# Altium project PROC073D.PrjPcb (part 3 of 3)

## Sheet PROC073D_Can_Interface.SchDoc: CAN Interface
size 431 x 279 mm; Date: Not shown in title block; ApprovedBy: Not shown in title block; CheckedBy: Not shown in title block; Author: Not shown in title block; CompanyName: Not shown in title block; DrawnBy: Charles F. Oladimeji; Engineer: Not shown in title block; Organization: Not shown in title block; Address1: Not shown in title block; Address2: Not shown in title block; Address3: Not shown in title block; Address4: Not shown in title block; DocumentNumber: 12; Revision: Use project parameter SCH_Rev; SheetNumber: 12; SheetTotal: 13; PageSetup: Record=PageOptions¦CenterHorizontal=True¦CenterVertical=True¦PrintScale=1.00¦XCorrection=1.00¦YCorrection=1.00¦PrintKind=0¦BorderSize=5000000¦LeftOffset=0¦BottomOffset=0¦Orientation=2¦PaperLength=1000¦PaperWidth=1000¦Scale=100¦PaperSource=15¦PrintQuality=600¦MediaType=1¦DitherType=10¦PaperKind=Letter¦PrintScaleMode=1
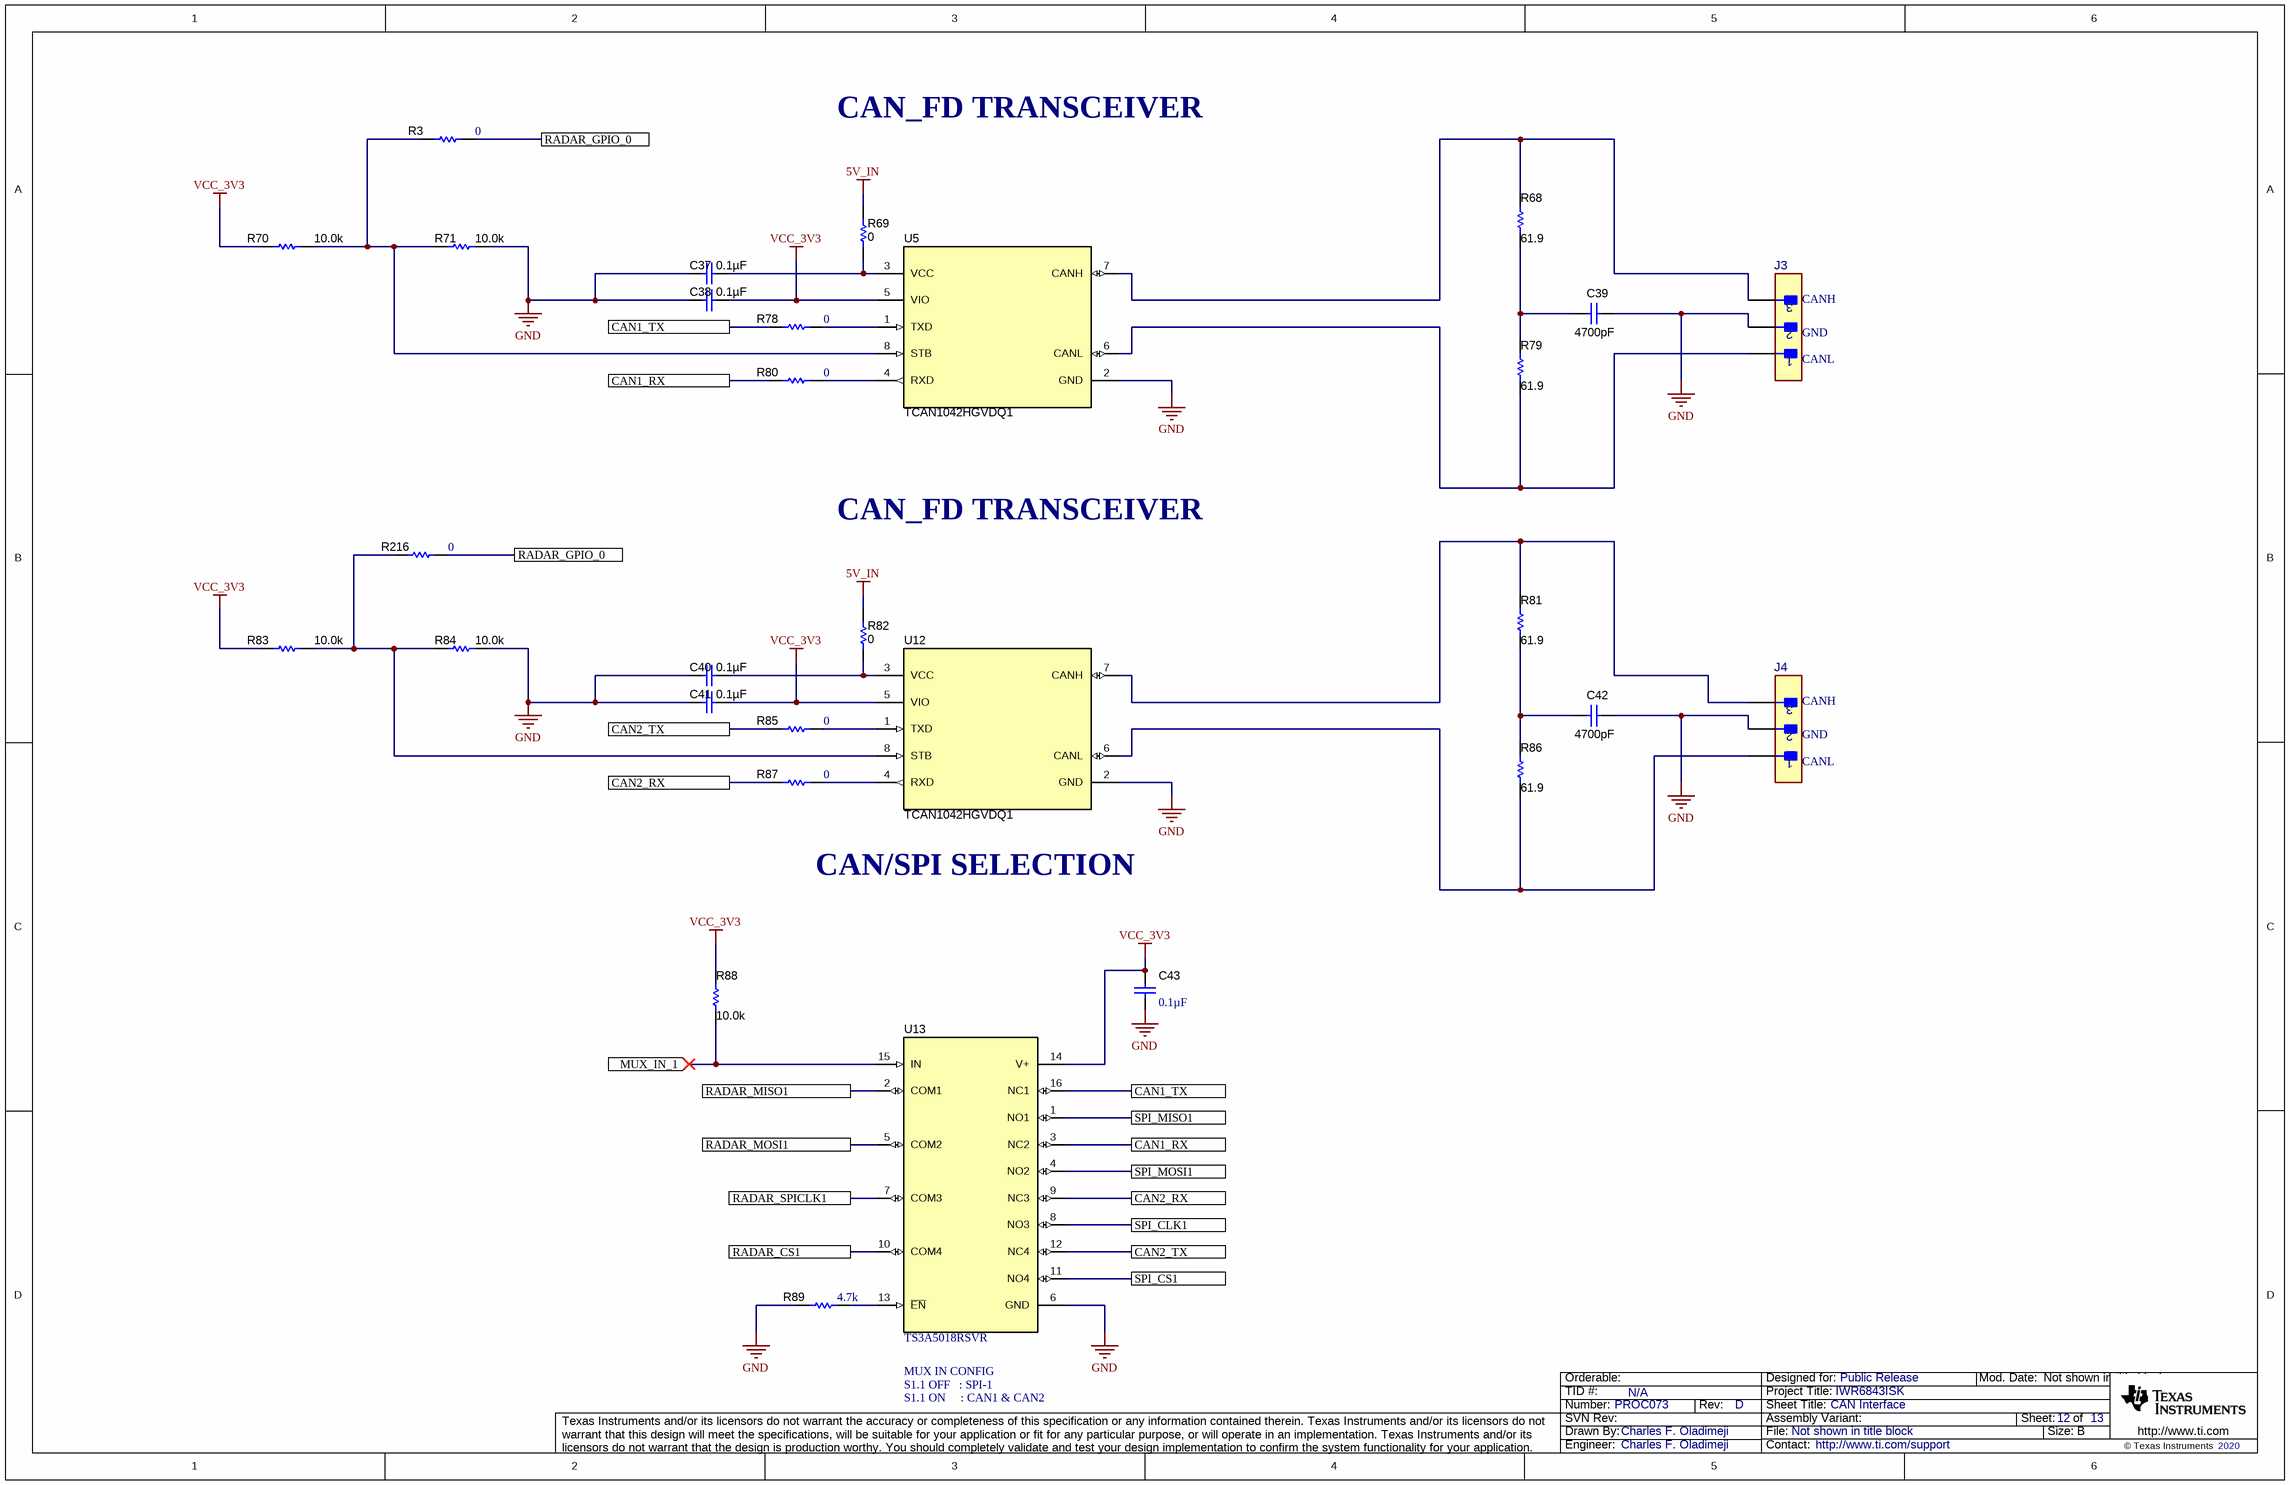
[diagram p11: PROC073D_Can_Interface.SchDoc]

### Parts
C37  ValueDisplayed: 0.1µF  [0402L]  (hidden comment: C0402C104K8RACTU)
C38  ValueDisplayed: 0.1µF  [0402L]  (hidden comment: C0402C104K8RACTU)
C39  ValueDisplayed: 4700pF  [0402L]  (hidden comment: GCM155R71H472KA37D)
C40  ValueDisplayed: 0.1µF  [0402L]  (hidden comment: C0402C104K8RACTU)
C41  ValueDisplayed: 0.1µF  [0402L]  (hidden comment: C0402C104K8RACTU)
C42  ValueDisplayed: 4700pF  [0402L]  (hidden comment: GCM155R71H472KA37D)
C43  ValueDisplayed: 0.1µF  [0402]  (hidden comment: C0402C104K8RACTU)
J3  M50-3930342  [FP-M50-3930342_HDR3-MFG]  (value not drawn)
J4  M50-3930342  [FP-M50-3930342_HDR3-MFG]  (value not drawn)
R3  ValueDisplayed: 0  [0402]  (hidden comment: ERJ-2GE0R00X)
R68  ValueDisplayed: 61.9  [0402L]  (hidden comment: CRCW040261R9FKED)
R69  ValueDisplayed: 0  [0201_Silk]  (hidden comment: CRCW02010000Z0ED)
R70  ValueDisplayed: 10.0k  [0402L]  (hidden comment: CRCW040210K0FKED)
R71  ValueDisplayed: 10.0k  [0402L]  (hidden comment: CRCW040210K0FKED)
R78  ValueDisplayed: 0  [0402]  (hidden comment: ERJ-2GE0R00X)
R79  ValueDisplayed: 61.9  [0402L]  (hidden comment: CRCW040261R9FKED)
R80  ValueDisplayed: 0  [0402]  (hidden comment: ERJ-2GE0R00X)
R81  ValueDisplayed: 61.9  [0402L]  (hidden comment: CRCW040261R9FKED)
R82  ValueDisplayed: 0  [0201_Silk]  (hidden comment: CRCW02010000Z0ED)
R83  ValueDisplayed: 10.0k  [0402L]  (hidden comment: CRCW040210K0FKED)
R84  ValueDisplayed: 10.0k  [0402L]  (hidden comment: CRCW040210K0FKED)
R85  ValueDisplayed: 0  [0402]  (hidden comment: ERJ-2GE0R00X)
R86  ValueDisplayed: 61.9  [0402L]  (hidden comment: CRCW040261R9FKED)
R87  ValueDisplayed: 0  [0402]  (hidden comment: ERJ-2GE0R00X)
R88  ValueDisplayed: 10.0k  [0402L]  (hidden comment: CRCW040210K0FKED)
R89  ValueDisplayed: 4.7k  [0402]  (hidden comment: CRCW04024K70JNED)
R216  ValueDisplayed: 0  [0402]  (hidden comment: ERJ-2GE0R00X)
U5  TCAN1042HGVDQ1  [D0008A_L]
U12  TCAN1042HGVDQ1  [D0008A_L]
U13  TS3A5018RSVR  [RSV0016A]

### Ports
CAN1_RX, CAN1_TX, CAN2_RX, CAN2_TX, MUX_IN_1 (in), RADAR_CS1, RADAR_GPIO_0, RADAR_MISO1, RADAR_MOSI1, RADAR_SPICLK1, SPI_CLK1, SPI_CS1, SPI_MISO1, SPI_MOSI1

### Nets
5V_IN: R69.2 R82.2
GND: C37.1 C38.1 C39.1 C40.1 C41.1 C42.1 C43.2 J3.2 J4.2 R71.2 R84.2 R89.1 U5.2(GND) U12.2(GND) U13.6(GND)
VCC_3V3: C38.2 C41.2 C43.1 R70.1 R83.1 R88.2 U5.5(VIO) U12.5(VIO) U13.14(V+)
CAN1_RX: R80.1 U13.3(NC2) ; port CAN1_RX
CAN1_TX: R78.1 U13.16(NC1) ; port CAN1_TX
CAN2_RX: R87.1 U13.9(NC3) ; port CAN2_RX
CAN2_TX: R85.1 U13.12(NC4) ; port CAN2_TX
MUX_IN_1: R88.1 U13.15(IN) ; port MUX_IN_1
RADAR_CS1: U13.10(COM4) ; port RADAR_CS1
RADAR_GPIO_0: R3.2 R216.2 ; port RADAR_GPIO_0
RADAR_MISO1: U13.2(COM1) ; port RADAR_MISO1
RADAR_MOSI1: U13.5(COM2) ; port RADAR_MOSI1
RADAR_SPICLK1: U13.7(COM3) ; port RADAR_SPICLK1
SPI_CLK1: U13.8(NO3) ; port SPI_CLK1
SPI_CS1: U13.11(NO4) ; port SPI_CS1
SPI_MISO1: U13.1(NO1) ; port SPI_MISO1
SPI_MOSI1: U13.4(NO2) ; port SPI_MOSI1
NetC37_2: C37.2 R69.1 U5.3(VCC)
NetC39_2: C39.2 R68.1 R79.2
NetC40_2: C40.2 R82.1 U12.3(VCC)
NetC42_2: C42.2 R81.1 R86.2
NetJ3_1: J3.1 R79.1 U5.6(CANL)
NetJ3_3: J3.3 R68.2 U5.7(CANH)
NetJ4_1: J4.1 R86.1 U12.6(CANL)
NetJ4_3: J4.3 R81.2 U12.7(CANH)
NetR3_1: R3.1 R70.2 R71.1 U5.8(STB)
NetR78_2: R78.2 U5.1(TXD)
NetR80_2: R80.2 U5.4(RXD)
NetR83_2: R83.2 R84.1 R216.1 U12.8(STB)
NetR85_2: R85.2 U12.1(TXD)
NetR87_2: R87.2 U12.4(RXD)
NetR89_2: R89.2 U13.13(~{EN})

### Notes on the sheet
- CAN_FD TRANSCEIVER
- (near J3) CANH
- (near J3) GND
- (near J3) CANL
- (near J4) CANH
- (near J4) GND
- (near J4) CANL
- CAN/SPI SELECTION
- MUX IN CONFIG
- S1.1 OFF   : SPI-1
- S1.1 ON     : CAN1 & CAN2

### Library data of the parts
C37 C38 C40 C41 = CMP-0078241-1: CAP, CERM, 0.1 µF, 10 V,+/- 10%, X7R, 0402; Manufacturer: Kemet; TaMin_C: -55°C; Polarized: N; SizeAreaWB_mm2: 3; U/M: EA; Value: 0.1uF; TaMax_C: 125°C; SizeZ_mm: 0.6; SizeX_mm: 1; SizeY_mm: 0.5; Cap_Case: 0402; Value2: 10V; CompType: Capacitor; Cap_F: 100nF; AEC Category: Q200
C39 C42 = CMP-0006361-2: CAP, CERM, 4700 pF, 50 V, +/- 10%, X7R, AEC-Q200 Grade 1, 0402; Manufacturer: MuRata; TaMin_C: -55°C; Polarized: N; SizeAreaWB_mm2: 3; Value1: Unknown; U/M: EA; Value: 4700pF; TaMax_C: 125°C; SizeZ_mm: 0.6; SizeX_mm: 1; SizeY_mm: 0.5; Cap_Case: 0402; Value2: 50V; AEC Qualified: Y; Cap_F: 4.7nF; AEC Category: Q200
C43 = CMP-0078241-1: CAP, CERM, 0.1 µF, 10 V,+/- 10%, X7R, 0402; Manufacturer: Kemet; TaMin_C: -55°C; Polarized: N; SizeAreaWB_mm2: 3; U/M: EA; Value: 0.1uF; TaMax_C: 125°C; SizeZ_mm: 0.6; SizeX_mm: 1; SizeY_mm: 0.5; Value2: 10V; CompType: Capacitor; Cap_F: 100nF; AEC Category: Q200
J3 J4 = CMP-0087785-1: CONN HEADER R/A 3POS 1.27MM; Manufacturer: Harwin; Row_Count: 1; Current_A: 1A; ContactFinish: Gold,Nickel
R3 R78 R80 R85 R87 R216 = CMP-0026992-3: RES, 0, 5%, 0.1 W, AEC-Q200 Grade 0, 0402; Manufacturer: Panasonic; Power_W: 100mW; TempCo: 600 ppm/C; Value_Code: 0000; Value: 0; EIA_Code: E24; SizeX_mm: 1; SizeY_mm: 0.5; SizeZ_mm: 0.6; Value2: 0.1W; CompType: Resistor; AEC Qualified: Y; VDC_V: 50V; AEC Category: Q200; SizeAreaWB_mm2: 3; INSTALLATION: DNP
R68 R79 R81 R86 = CMP-0026491-2: RES, 61.9, 1%, 0.063 W, AEC-Q200 Grade 0, 0402; Manufacturer: Vishay-Dale; Power_W: 63mW; TempCo: 100 ppm/C; Value_Code: 61R9; Value: 61.9; EIA_Code: E96; SizeX_mm: 1; SizeY_mm: 0.5; SizeZ_mm: 0.6; Value2: 0.063W; AEC Qualified: Y; VDC_V: 50V; AEC Category: Q200; AEC Grade: 0
R69 R82 = CMP-0027008-4: RES, 0, 5%, 0.05 W, 0201; Manufacturer: Vishay-Dale; Power_W: 50mW; TempCo: ppm/C; Value_Code: 0000; Value: 0; EIA_Code: E24; SizeX_mm: 0.6; SizeY_mm: 0.3; SizeZ_mm: 0.26; Value2: 0.05W; SizeArea_mm2: 0.18; AEC Qualified: N; AEC Category: Q200
R70 R71 R83 R84 R88 = CMP-0025958-3: RES, 10.0 k, 1%, 0.063 W, AEC-Q200 Grade 0, 0402; Manufacturer: Vishay-Dale; Power_W: 63mW; TempCo: 100 ppm/C; Value_Code: 10k0; Value: 10.0k; EIA_Code: E96; Res_ohm: 10k; SizeX_mm: 1; SizeY_mm: 0.5; SizeZ_mm: 0.6; Value2: 0.063W; AEC Qualified: Y; VDC_V: 50V; AEC Category: Q200; AEC Grade: 0
R89 = CMP-0026938-5: RES, 4.7 k, 5%, 0.063 W, AEC-Q200 Grade 0, 0402; Manufacturer: Vishay-Dale; Power_W: 63mW; TempCo: 200 ppm/C; Value_Code: 4k70; Value: 4.7k; EIA_Code: E24; SizeX_mm: 1; SizeY_mm: 0.5; SizeZ_mm: 0.6; Value2: 0.063W; AEC Qualified: Y; VDC_V: 50V; AEC Category: Q200; AEC Grade: 0
U5 U12 = CMP-0075992-1: Automotive Fault Protected CAN Transceiver With Flexible Data-Rate, D0008A (SOIC-8); Manufacturer: Texas Instruments; Alternate PartNumber: TCAN1042HGVDRQ1; SizeAreaWB_mm2: 56.58; SizeArea_mm2: 30.38; SizeZ_mm: 1.75; SizeY_mm: 6.2; U/M: EA; CompType: IC; SizeX_mm: 4.9
U13 = CMP-0067415-1: 10-Ohm Quad SPDT Analog Switch, RSV0016A (UQFN-16); Alternate Manufacturer: Texas Instruments; SizeAreaWB_mm2: 10.08; U/M: EA; SizeZ_mm: 0.55; SizeX_mm: 1.8; SizeY_mm: 2.6; SizeArea_mm2: 4.68; CompType: IC

## Sheet PROC073D_EVM_Hardware.SchDoc: Hardware
size 431 x 279 mm; Date: Not shown in title block; ApprovedBy: Not shown in title block; CheckedBy: Not shown in title block; Author: Not shown in title block; CompanyName: Not shown in title block; DrawnBy: Charles F. Oladimeji; Engineer: Not shown in title block; Organization: Not shown in title block; Address1: Not shown in title block; Address2: Not shown in title block; Address3: Not shown in title block; Address4: Not shown in title block; DocumentNumber: 13; Revision: Use project parameter SCH_Rev; SheetNumber: 13; SheetTotal: 13; PageSetup: Record=PageOptions¦CenterHorizontal=True¦CenterVertical=True¦PrintScale=1.00¦XCorrection=1.00¦YCorrection=1.00¦PrintKind=0¦BorderSize=5000000¦LeftOffset=0¦BottomOffset=0¦Orientation=2¦PaperLength=1000¦PaperWidth=1000¦Scale=100¦PaperSource=15¦PrintQuality=600¦MediaType=1¦DitherType=10¦PaperKind=Letter¦PrintScaleMode=1
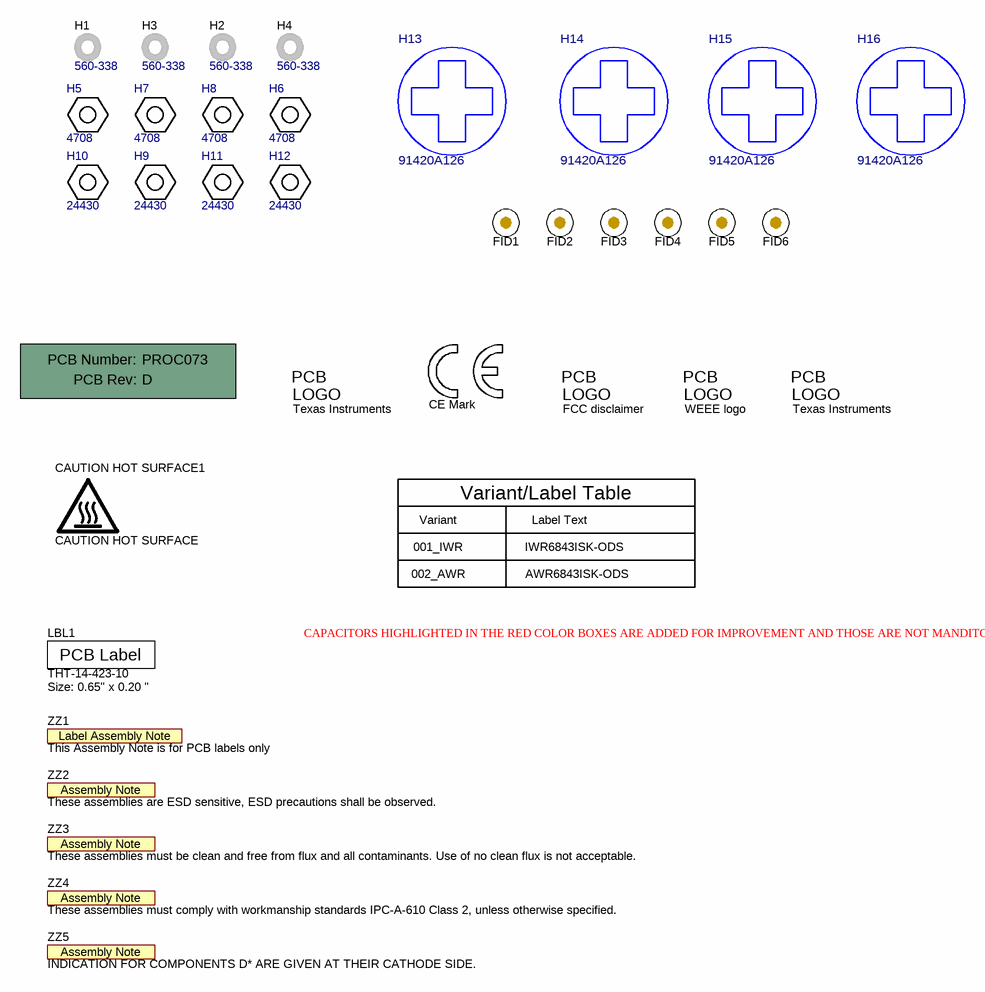
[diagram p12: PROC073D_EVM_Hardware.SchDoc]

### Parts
!PCB  Printed Circuit Board  (value not drawn)  (mechanical)
CAUTION_HOT_SURFACE1  CAUTION HOT SURFACE  [IEC_HotSurface_Small]  (no BOM)
FID1  Fiducial  [Fiducial10-20]  (value not drawn)
FID2  Fiducial  [Fiducial10-20]  (value not drawn)
FID3  Fiducial  [Fiducial10-20]  (value not drawn)
FID4  Fiducial  [Fiducial10-20]  (value not drawn)
FID5  Fiducial  [Fiducial10-20]  (value not drawn)
FID6  Fiducial  [Fiducial10-20]  (value not drawn)
H1  560-338  (mechanical)
H2  560-338  (mechanical)
H3  560-338  (mechanical)
H4  560-338  (mechanical)
H5  4708  (mechanical)
H6  4708  (mechanical)
H7  4708  (mechanical)
H8  4708  (mechanical)
H9  24430  (mechanical)
H10  24430  (mechanical)
H11  24430  (mechanical)
H12  24430  (mechanical)
H13  91420A126  [FP-91420A126_SCREW_M3X0.5-MFG]  (mechanical)
H14  91420A126  [FP-91420A126_SCREW_M3X0.5-MFG]  (mechanical)
H15  91420A126  [FP-91420A126_SCREW_M3X0.5-MFG]  (mechanical)
H16  91420A126  [FP-91420A126_SCREW_M3X0.5-MFG]  (mechanical)
LBL1  THT-14-423-10  Note: Size: 0.65" x 0.20 "  [Label_650x200]
Logo1  Texas Instruments  [TI_Stacked_Overlay_Small]  (no BOM)
Logo2  CE Mark  [CE_Mark_5mm]  (no BOM)
Logo3  FCC disclaimer  [FCC_disclaimer]  (no BOM)
Logo4  WEEE logo  [WEEE_Minimum]  (no BOM)
Logo5  Texas Instruments  [TI_Symbol_Overlay_Small]  (no BOM)
ZZ1  This Assembly Note is for PCB labels only  [AssemblyNoteLabel]  (no BOM)
ZZ2  These assemblies are ESD sensitive, ESD precautions shall be observed.  [AssemblyNote]  (no BOM)
ZZ3  These assemblies must be clean and free from flux and all contaminants. Use of no clean flux is not acceptable.  [AssemblyNote]  (no BOM)
ZZ4  These assemblies must comply with workmanship standards IPC-A-610 Class 2, unless otherwise specified.  [AssemblyNote]  (no BOM)
ZZ5  INDICATION FOR COMPONENTS D* ARE GIVEN AT THEIR CATHODE SIDE.  [AssemblyNote]  (no BOM)

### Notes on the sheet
- Variant
- 001_IWR
- Variant/Label Table
- Label Text
- IWR6843ISK-ODS
- 002_AWR
- AWR6843ISK-ODS
- CAPACITORS HIGHLIGHTED IN THE RED COLOR BOXES ARE ADDED FOR IMPROVEMENT AND THOSE ARE NOT MANDITORY.

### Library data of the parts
!PCB = CMP-0003618-2: Manufacturer: Any; PartNumber: PROC073
CAUTION_HOT_SURFACE1 = CMP-0074837-1: IEC 61010-1 Hot Surface Warning; Library Reference: IEC_HotSurface; SymbolCreator: a0412235
FID1-FID6 = CMP-0077181-1: Fiducial mark.  There is nothing to buy or mount.
H1-H4 = CMP-0084015-1: Steel Plain Washer; Manufacturer: RS Pro
H5-H8 = CMP-0003742-1: HEX NUT 0.217" STEEL M3; Manufacturer: Keystone; CompType: Standoff
H9-H12 = CMP-0003759-1: HEX Standoff M3 Aluminum 5 MM; Manufacturer: Keystone
H13-H16 = CMP-0086605-1: Steel Phillips Flat Head Screws M3 x 0.5 mm Thread, 16 mm Long; Manufacturer: McMaster-Carr
LBL1 = CMP-0003625-1: Thermal Transfer Printable Labels, 0.650" W x 0.200" H - 10,000 per roll; Manufacturer: Brady; CompType: Label
Logo1 = CMP-0074838-1: Texas Instrument Corporate Signature; SymbolCreator: a0412235; Lib Reference: TI_Logo; Library Reference: Logo
Logo2 = CMP-0074844-1: SymbolCreator: a0412235
Logo3 = CMP-0074847-1: FCC_disclaimer; Library Reference: Logo
Logo4 = CMP-0074769-1
Logo5 = CMP-0074838-1: Texas Instrument Corporate Signature; Library Reference: Logo; SymbolCreator: a0412235; Lib Reference: TI_Logo
ZZ1 = CMP-0003616-3
ZZ2 = CMP-0077236-1
ZZ3 = CMP-0077237-1
ZZ4 ZZ5 = CMP-0077238-1

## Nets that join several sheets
5V_IN: PROC073D_PMIC (12 pins), PROC073D_Flash_USB_To_UART (D2.1 R90.1), PROC073D_HD_DCA_Conn (R141.1), PROC073D_Can_Interface (R69.2 R82.2)
CB_PMIC_1V0: PROC073D_PMIC (R199.2), PROC073D_Decoupling_caps (C2.2 C3.2 L2.1 L3.1), PROC073D_HD_Connector_60Pin (J1.1 J1.3), PROC073D_Temp_Current_sensor (U7.9)
CB_PMIC_1V2: PROC073D_PMIC (R193.2), PROC073D_Decoupling_caps (C64.2 L7.1), PROC073D_HD_Connector_60Pin (J1.5 J1.7), PROC073D_Temp_Current_sensor (U8.9)
CB_PMIC_1V8: PROC073D_PMIC (R192.2 R195.1), PROC073D_Decoupling_caps (C1.2 L1.1), PROC073D_HD_Connector_60Pin (J1.9), PROC073D_Temp_Current_sensor (U6.9)
CONN_5V: PROC073D_HD_Connector_60Pin (J1.2 J2.58 J2.59 J2.60), PROC073D_Flash_USB_To_UART (C50.1 R102.1 U16.8), PROC073D_HD_DCA_Conn (8 pins)
GND: PROC073D_PMIC (34 pins), PROC073D_IWR6843_Chip (77 pins), PROC073D_Decoupling_caps (46 pins), PROC073D_QSPI_Flash_section (C34.1 C35.1 U2.4 U2.9), PROC073D_HD_Connector_60Pin (23 pins), PROC073D_Temp_Current_sensor (23 pins), PROC073D_Flash_USB_To_UART (28 pins), PROC073D_HD_DCA_Conn (26 pins), PROC073D_SOP_Ctrl (5 pins), PROC073D_Can_Interface (15 pins)
PMIC_1V0: PROC073D_PMIC (5 pins), PROC073D_Temp_Current_sensor (U7.8 U7.10)
PMIC_1V2: PROC073D_PMIC (5 pins), PROC073D_Temp_Current_sensor (U8.8 U8.10)
PMIC_1V8: PROC073D_PMIC (5 pins), PROC073D_Temp_Current_sensor (U6.8 U6.10)
PMICOUT_3V3: PROC073D_PMIC (L11.1 R198.2 TP10.1), PROC073D_Flash_USB_To_UART (9 pins), PROC073D_SOP_Ctrl (S1.10 S1.11 S1.12)
RADAR_1P0_RF1: PROC073D_IWR6843_Chip (U1.G5 U1.H5 U1.J5), PROC073D_Decoupling_caps (7 pins)
RADAR_1P0_RF2: PROC073D_IWR6843_Chip (U1.C2 U1.D2), PROC073D_Decoupling_caps (8 pins)
RADAR_1V2: PROC073D_IWR6843_Chip (6 pins), PROC073D_Decoupling_caps (9 pins)
RADAR_1V4_APLL: PROC073D_IWR6843_Chip (U1.A10), PROC073D_Decoupling_caps (C22.2)
RADAR_1V4_SYNTH: PROC073D_IWR6843_Chip (U1.B13), PROC073D_Decoupling_caps (C18.2)
RADAR_1V8: PROC073D_IWR6843_Chip (6 pins), PROC073D_Decoupling_caps (11 pins)
RADAR_3V3: PROC073D_PMIC (R184.2 R200.2), PROC073D_IWR6843_Chip (7 pins), PROC073D_Decoupling_caps (5 pins), PROC073D_Temp_Current_sensor (U10.9)
RADAR_VBGAP: PROC073D_IWR6843_Chip (U1.B10), PROC073D_Decoupling_caps (C6.1)
RADAR_VOUT_PA: PROC073D_IWR6843_Chip (U1.A2 U1.B2), PROC073D_Decoupling_caps (5 pins)
VCC_3V3: PROC073D_PMIC (7 pins), PROC073D_QSPI_Flash_section (R43.2 R44.2 R49.2 R50.1), PROC073D_HD_Connector_60Pin (6 pins), PROC073D_Temp_Current_sensor (27 pins), PROC073D_HD_DCA_Conn (6 pins), PROC073D_Can_Interface (9 pins)
VCC_LD_SW_3V3: PROC073D_PMIC (6 pins), PROC073D_Temp_Current_sensor (U10.8 U10.10)
VPP_1P7: PROC073D_IWR6843_Chip (C31.2 U1.L13), PROC073D_HD_Connector_60Pin (J2.57 TP14.1)
CONN_RS232RX: PROC073D_HD_Connector_60Pin (R38.1), PROC073D_Flash_USB_To_UART (U15.7), PROC073D_HD_DCA_Conn (J6.55)
CONN_RS232TX: PROC073D_HD_Connector_60Pin (R40.1), PROC073D_Flash_USB_To_UART (U15.9), PROC073D_HD_DCA_Conn (J6.57)
MUX_IN_1: PROC073D_SOP_Ctrl (S1.4), PROC073D_Can_Interface (R88.1 U13.15)
MUX_IN_2: PROC073D_Flash_USB_To_UART (R100.1 U15.1 U15.5), PROC073D_SOP_Ctrl (S1.5)
PGOOD: PROC073D_PMIC (R179.1 R182.2 R198.1 R201.2), PROC073D_HD_Connector_60Pin (R13.2), PROC073D_HD_DCA_Conn (J6.13)
PMIC_CLK: PROC073D_PMIC (U4.3), PROC073D_SOP_Ctrl (R202.2)
PMIC_EN1: PROC073D_PMIC (R188.1 U4.7), PROC073D_HD_Connector_60Pin (R140.1)
RADAR_BSS_LOGGER: PROC073D_IWR6843_Chip (U1.H14), PROC073D_HD_Connector_60Pin (R60.2)
RADAR_CS1: PROC073D_IWR6843_Chip (R156.1 U1.E15), PROC073D_Can_Interface (U13.10)
RADAR_DMM_CLK: PROC073D_IWR6843_Chip (U1.N15), PROC073D_HD_Connector_60Pin (R15.1), PROC073D_HD_DCA_Conn (J6.15)
RADAR_DMM_SYNC: PROC073D_IWR6843_Chip (U1.N14), PROC073D_HD_Connector_60Pin (R17.1), PROC073D_HD_DCA_Conn (J6.17)
RADAR_DP0: PROC073D_IWR6843_Chip (U1.R4), PROC073D_HD_Connector_60Pin (R18.1), PROC073D_HD_DCA_Conn (J6.19)
RADAR_DP1: PROC073D_IWR6843_Chip (U1.P5), PROC073D_HD_Connector_60Pin (R19.1), PROC073D_HD_DCA_Conn (J6.21)
RADAR_DP2: PROC073D_IWR6843_Chip (U1.R5), PROC073D_HD_Connector_60Pin (R20.1), PROC073D_HD_DCA_Conn (J6.23)
RADAR_DP3: PROC073D_IWR6843_Chip (U1.P6), PROC073D_HD_Connector_60Pin (R21.1), PROC073D_HD_DCA_Conn (J6.25)
RADAR_DP4: PROC073D_IWR6843_Chip (U1.R7), PROC073D_HD_Connector_60Pin (R23.1), PROC073D_HD_DCA_Conn (J6.27)
RADAR_DP5: PROC073D_IWR6843_Chip (U1.P7), PROC073D_HD_Connector_60Pin (R26.1), PROC073D_HD_DCA_Conn (J6.29)
RADAR_DP6: PROC073D_IWR6843_Chip (U1.R8), PROC073D_HD_Connector_60Pin (R27.1), PROC073D_HD_DCA_Conn (J6.31)
RADAR_DP7: PROC073D_IWR6843_Chip (U1.P8), PROC073D_HD_Connector_60Pin (R28.1), PROC073D_HD_DCA_Conn (J6.33)
RADAR_DP8: PROC073D_HD_Connector_60Pin (R124.1), PROC073D_HD_DCA_Conn (R148.1)
RADAR_DP9: PROC073D_HD_Connector_60Pin (R125.1), PROC073D_HD_DCA_Conn (R149.1)
RADAR_DP10: PROC073D_HD_Connector_60Pin (R126.1), PROC073D_HD_DCA_Conn (R163.1)
RADAR_DP11: PROC073D_HD_Connector_60Pin (R127.1), PROC073D_HD_DCA_Conn (R164.1)
RADAR_DP12: PROC073D_HD_Connector_60Pin (R128.1), PROC073D_HD_DCA_Conn (R166.1)
RADAR_DP13: PROC073D_HD_Connector_60Pin (R129.1), PROC073D_HD_DCA_Conn (R167.1)
RADAR_DP14: PROC073D_HD_Connector_60Pin (R130.1), PROC073D_HD_DCA_Conn (R168.1)
RADAR_DP15: PROC073D_HD_Connector_60Pin (R132.1), PROC073D_HD_DCA_Conn (R170.1)
RADAR_GPIO_0: PROC073D_IWR6843_Chip (U1.H13), PROC073D_HD_Connector_60Pin (R65.1), PROC073D_Can_Interface (R3.2 R216.2)
RADAR_GPIO_1: PROC073D_IWR6843_Chip (U1.J13), PROC073D_HD_Connector_60Pin (R66.2), PROC073D_HD_DCA_Conn (R214.2)
RADAR_GPIO_2: PROC073D_PMIC (R185.2), PROC073D_IWR6843_Chip (U1.K13), PROC073D_HD_Connector_60Pin (R67.2), PROC073D_HD_DCA_Conn (D7.1)
RADAR_HOSTINTR1: PROC073D_IWR6843_Chip (R152.2 U1.P13), PROC073D_HD_Connector_60Pin (R10.2), PROC073D_HD_DCA_Conn (J6.10)
RADAR_LVDS_0M: PROC073D_IWR6843_Chip (U1.J15), PROC073D_HD_Connector_60Pin (R41.2), PROC073D_HD_DCA_Conn (R230.2)
RADAR_LVDS_0P: PROC073D_IWR6843_Chip (U1.J14), PROC073D_HD_Connector_60Pin (R39.2), PROC073D_HD_DCA_Conn (R229.2)
RADAR_LVDS_1M: PROC073D_IWR6843_Chip (U1.K15), PROC073D_HD_Connector_60Pin (R35.2), PROC073D_HD_DCA_Conn (R228.2)
RADAR_LVDS_1P: PROC073D_IWR6843_Chip (U1.K14), PROC073D_HD_Connector_60Pin (R33.2), PROC073D_HD_DCA_Conn (R227.2)
RADAR_LVDS_2M: PROC073D_HD_Connector_60Pin (R137.2), PROC073D_HD_DCA_Conn (R224.2)
RADAR_LVDS_2P: PROC073D_HD_Connector_60Pin (R136.2), PROC073D_HD_DCA_Conn (R223.2)
RADAR_LVDS_3M: PROC073D_HD_Connector_60Pin (R135.2), PROC073D_HD_DCA_Conn (R222.2)
RADAR_LVDS_3P: PROC073D_HD_Connector_60Pin (R134.2), PROC073D_HD_DCA_Conn (R221.2)
RADAR_LVDS_CLKM: PROC073D_IWR6843_Chip (U1.L15), PROC073D_HD_Connector_60Pin (R32.2), PROC073D_HD_DCA_Conn (R226.2)
RADAR_LVDS_CLKP: PROC073D_IWR6843_Chip (U1.L14), PROC073D_HD_Connector_60Pin (R30.2), PROC073D_HD_DCA_Conn (R225.2)
RADAR_LVDS_FRCLKM: PROC073D_IWR6843_Chip (U1.M15), PROC073D_HD_Connector_60Pin (R24.2), PROC073D_HD_DCA_Conn (R220.2)
RADAR_LVDS_FRCLKP: PROC073D_IWR6843_Chip (U1.M14), PROC073D_HD_Connector_60Pin (R22.2), PROC073D_HD_DCA_Conn (R219.2)
RADAR_LVDS_VALIDM: PROC073D_HD_Connector_60Pin (R133.2), PROC073D_HD_DCA_Conn (R218.2)
RADAR_LVDS_VALIDP: PROC073D_HD_Connector_60Pin (R131.2), PROC073D_HD_DCA_Conn (R217.2)
RADAR_MCUCLKOUT: PROC073D_IWR6843_Chip (U1.N8), PROC073D_HD_Connector_60Pin (R62.2)
RADAR_MISO1: PROC073D_IWR6843_Chip (U1.E14), PROC073D_Can_Interface (U13.2)
RADAR_MOSI1: PROC073D_IWR6843_Chip (U1.D13), PROC073D_Can_Interface (U13.5)
RADAR_MSS_LOGGER: PROC073D_IWR6843_Chip (U1.F14), PROC073D_HD_Connector_60Pin (R31.2), PROC073D_Flash_USB_To_UART (R96.2)
RADAR_NERR_OUT: PROC073D_IWR6843_Chip (R169.1 U1.N6), PROC073D_HD_Connector_60Pin (R59.2)
RADAR_NERRIN: PROC073D_IWR6843_Chip (R150.1 U1.N7), PROC073D_HD_Connector_60Pin (R58.2)
RADAR_NRST: PROC073D_IWR6843_Chip (U1.R3), PROC073D_HD_DCA_Conn (R171.1 U17.4)
RADAR_NRST_1: PROC073D_HD_Connector_60Pin (R42.1), PROC073D_HD_DCA_Conn (J6.59 R123.2 U17.1)
RADAR_OSC_CLKOUT: PROC073D_IWR6843_Chip (U1.A14), PROC073D_HD_Connector_60Pin (R61.2)
RADAR_PMIC_CLKOUT_SOP2: PROC073D_IWR6843_Chip (U1.P9), PROC073D_HD_Connector_60Pin (R63.2), PROC073D_SOP_Ctrl (R202.1 R203.1)
RADAR_QSPI_CS: PROC073D_IWR6843_Chip (U1.P11), PROC073D_QSPI_Flash_section (R50.2 U2.1)
RADAR_QSPI_D0: PROC073D_IWR6843_Chip (U1.R13), PROC073D_QSPI_Flash_section (R45.2)
RADAR_QSPI_D1: PROC073D_IWR6843_Chip (U1.N12), PROC073D_QSPI_Flash_section (R46.1)
RADAR_QSPI_D2: PROC073D_IWR6843_Chip (U1.R14), PROC073D_QSPI_Flash_section (R44.1 R47.1)
RADAR_QSPI_D3: PROC073D_IWR6843_Chip (U1.P12), PROC073D_QSPI_Flash_section (R49.1 R51.2)
RADAR_QSPI_SCLK: PROC073D_IWR6843_Chip (U1.R12), PROC073D_QSPI_Flash_section (R48.2)
RADAR_RS232RX: PROC073D_IWR6843_Chip (R154.1 U1.N4), PROC073D_Flash_USB_To_UART (U15.6)
RADAR_RS232TX: PROC073D_IWR6843_Chip (R153.1 U1.N5), PROC073D_Flash_USB_To_UART (U15.10)
RADAR_SCL: PROC073D_PMIC (R181.1), PROC073D_IWR6843_Chip (U1.G14), PROC073D_HD_Connector_60Pin (R37.1 R53.1), PROC073D_Temp_Current_sensor (6 pins), PROC073D_HD_DCA_Conn (J6.53)
RADAR_SDA: PROC073D_PMIC (R180.1), PROC073D_IWR6843_Chip (U1.F13), PROC073D_HD_Connector_60Pin (R34.1 R52.1), PROC073D_Temp_Current_sensor (6 pins), PROC073D_HD_DCA_Conn (J6.51)
RADAR_SPICLK1: PROC073D_IWR6843_Chip (U1.E13), PROC073D_Can_Interface (U13.7)
RADAR_SYNC_IN: PROC073D_IWR6843_Chip (R155.2 U1.P4), PROC073D_HD_Connector_60Pin (R36.2), PROC073D_HD_DCA_Conn (J6.16)
RADAR_SYNC_OUT_SOP1: PROC073D_IWR6843_Chip (U1.G13), PROC073D_HD_Connector_60Pin (R16.2), PROC073D_SOP_Ctrl (R206.1)
RADAR_TCK: PROC073D_IWR6843_Chip (U1.P10), PROC073D_HD_Connector_60Pin (R6.2)
RADAR_TDI: PROC073D_IWR6843_Chip (U1.R11), PROC073D_HD_Connector_60Pin (R5.1)
RADAR_TDO_SOP0: PROC073D_IWR6843_Chip (U1.N13), PROC073D_HD_Connector_60Pin (R4.2), PROC073D_SOP_Ctrl (R209.1)
RADAR_TMS: PROC073D_IWR6843_Chip (U1.N10), PROC073D_HD_Connector_60Pin (R8.2)
RADAR_WARMRST: PROC073D_IWR6843_Chip (U1.N9), PROC073D_HD_Connector_60Pin (R64.2)
SPI_CLK1: PROC073D_HD_Connector_60Pin (R9.1), PROC073D_HD_DCA_Conn (J6.9), PROC073D_Can_Interface (U13.8)
SPI_CS1: PROC073D_HD_Connector_60Pin (R7.1), PROC073D_HD_DCA_Conn (J6.7), PROC073D_Can_Interface (U13.11)
SPI_MISO1: PROC073D_HD_Connector_60Pin (R12.2), PROC073D_HD_DCA_Conn (J6.12), PROC073D_Can_Interface (U13.1)
SPI_MOSI1: PROC073D_HD_Connector_60Pin (R11.1), PROC073D_HD_DCA_Conn (J6.11), PROC073D_Can_Interface (U13.4)

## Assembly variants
001_IWR: not fitted C8 C40 C41 C42 C90 C91 C98 C99 C100 C103 FID1 FID2 FID3 FID4 FID5 FID6 J2 J4 R2 R3 R14 R57 R70 R81 R82 R83 R84 R85 R86 R87 R107 R113 R114 R116 R139 R147 R157 R161 R202 R216 TP14 U12
002_AWR: not fitted C8 C90 C91 C98 C99 C100 C103 FID1 FID2 FID3 FID4 FID5 FID6 J2 R2 R3 R14 R57 R70 R83 R107 R113 R114 R116 R139 R147 R157 R161 R202 TP14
